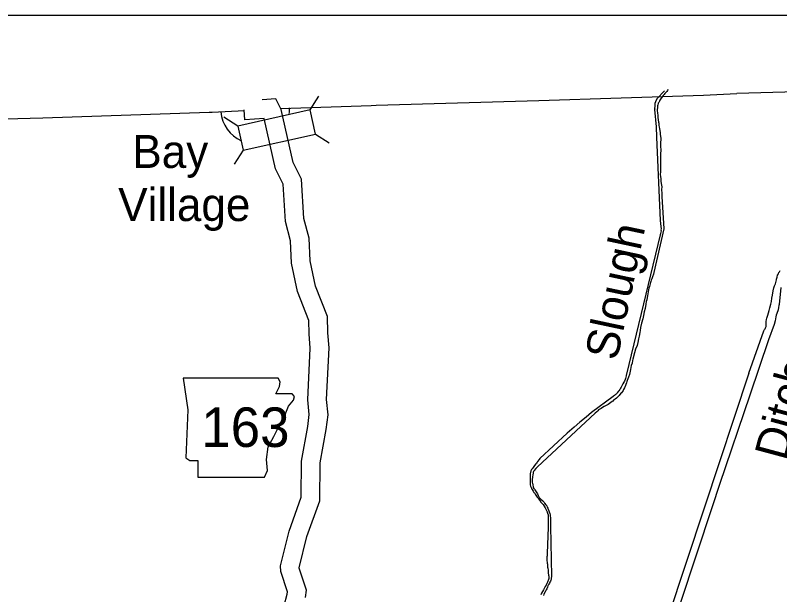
# Model space of a CAD drawing. Extents: x 1720274 to 1751788, y 372074 to 391887.
# Drawn here: x 1721650 to 1723587, y 389783 to 391250 of the extents above; entities that cross this region are included whole.
import ezdxf

# ---------------------------------------------------------------- set-up
doc = ezdxf.new("R2010")
doc.units = 0
for name, color, linetype in [('Level 10', 7, 'Continuous'), ('Level 2', 7, 'Continuous'), ('Level 20', 7, 'Continuous'), ('Level 21', 7, 'Continuous'), ('Level 24', 7, 'Continuous'), ('Level 9', 7, 'Continuous'), ('R_Draft', 7, 'Continuous')]:
    doc.layers.add(name, color=color, linetype=linetype)

msp = doc.modelspace()

# ---------------------------------------------------------------- linework, layer by layer
at = {"layer": 'Level 10'}
for points in [[(1722385.3, 389775.2), (1722387.6, 389794.5), (1722369.5, 389849.6), (1722369.5, 389850.5), (1722388.9, 389929.9), (1722421.2, 390020.6), (1722422.7, 390116.5), (1722437.8, 390201.2), (1722442.3, 390238.3), (1722438.3, 390277.1), (1722444.8, 390407.4), (1722442, 390446), (1722440.5, 390487.2), (1722410.2, 390563.9), (1722396.7, 390628.2), (1722394.2, 390685.6), (1722381.2, 390735.3), (1722375.2, 390834.5), (1722353.8, 390876.6), (1722323.9, 391011.1), (1722310.4, 391037.8), (1722275.4, 391035.3)], [(1722293, 389611.9), (1722338.6, 389784.2), (1722339.3, 389789.7), (1722322.4, 389841.3), (1722321.9, 389855.5), (1722343.5, 389943.5), (1722374, 390029.2), (1722375.3, 390121), (1722390.9, 390208.2), (1722394.6, 390238.8), (1722390.8, 390275.8), (1722397.4, 390406.8), (1722394.6, 390443.4), (1722393.4, 390477.3), (1722364.6, 390550.2), (1722349.5, 390622.2), (1722347, 390678.5), (1722334.1, 390727.8), (1722328.5, 390821.8), (1722308.8, 390860.5), (1722280.5, 390988.1), (1722231.4, 390984.6), (1722229.7, 391009.9)]]:
    msp.add_lwpolyline(points, dxfattribs=at)
at = {"layer": 'Level 2'}
for points in [[(1722322.5, 391013.9), (1722551.7, 391021.1), (1722564.3, 391022.3), (1722976.6, 391033.7), (1723393.7, 391047.3), (1723478.2, 391051.4)], [(1725918.9, 390953.1), (1725520.8, 390936.9), (1725105.9, 390920.6), (1725102.6, 390920.9), (1724681.3, 390898.6), (1724262.9, 390876.8), (1724258, 390877.1), (1723818.3, 390857.8), (1723811.7, 391060.7), (1723478.2, 391051.4)], [(1720701.8, 390842.8), (1720925, 390848.4), (1721339.8, 390867.2), (1721336.9, 390979.9), (1721719.6, 390989.9), (1722141.5, 391004.1), (1722148.7, 391004.5), (1722230.7, 391008.8)]]:
    msp.add_lwpolyline(points, dxfattribs=at)
at = {"layer": 'Level 20'}
for p, q in [((1722396.8, 391009.9), (1722419.2, 391045)), ((1722213.5, 390969.2), (1722178.3, 390991.6)), ((1722410.3, 390948.8), (1722445.5, 390926.4)), ((1722227.1, 390908.1), (1722204.7, 390872.9))]:
    msp.add_line(p, q, dxfattribs=at)
msp.add_lwpolyline([(1722227.1, 390908.1), (1722410.3, 390948.8), (1722396.8, 391009.9), (1722213.5, 390969.2)], close=True, dxfattribs=at)
at = {"layer": 'Level 21'}
msp.add_lwpolyline([(1722075.1, 390331.1), (1722087.1, 390250.9), (1722081.8, 390129.3), (1722092.5, 390122.6), (1722112.5, 390122.6), (1722112.5, 390079.9), (1722280.9, 390079.9), (1722289, 390097.2), (1722286.3, 390125.3), (1722290.3, 390157.4), (1722305, 390182.8), (1722314.3, 390201.5), (1722327.7, 390221.5), (1722335.7, 390242.9), (1722342.4, 390260.3), (1722354.4, 390275), (1722357.1, 390284.3), (1722351.8, 390291), (1722310.3, 390291), (1722319.7, 390309.7), (1722321, 390321.8), (1722315.5, 390331)], close=True, dxfattribs=at)
at = {"layer": 'Level 24'}
for start, end in [(352.9195, 2.5103), (184.1966, 246.5159)]:
    msp.add_arc((1722257.6, 391011.5), 86.9, start, end, dxfattribs=at)
at = {"layer": 'Level 9'}
for points in [[(1723294.7, 391058.5), (1723275.2, 391038.1), (1723272, 391030.5), (1723270.2, 391026), (1723270.1, 391024), (1723270, 391021.6), (1723270, 391018.9), (1723269.8, 391014.9), (1723269.9, 391011.9), (1723269.8, 391010.7), (1723273.7, 390967), (1723274.5, 390941.4), (1723283.7, 390730.4), (1723285.7, 390714.8), (1723286.2, 390709), (1723285.8, 390706.7), (1723285.9, 390703.9), (1723285.1, 390700.2), (1723284.6, 390697.5), (1723284.5, 390695.9), (1723284.1, 390693.7), (1723217.4, 390418.2), (1723197.7, 390337.5), (1723197.4, 390336.6), (1723196.9, 390333.4), (1723196.1, 390330.2), (1723194.7, 390327.4), (1723193.3, 390323.6), (1723191.6, 390320.7), (1723189.1, 390316.3), (1723187.5, 390312.8), (1723185.1, 390308.4), (1723183.5, 390305.2), (1723181.7, 390302), (1723178.8, 390298.7), (1723177.1, 390296.8), (1723175.1, 390293.7), (1723173.9, 390292.1), (1723172.2, 390290.6), (1723170.7, 390289.3), (1723168, 390286.8), (1723165.9, 390285.5), (1723164.6, 390284.6), (1723109.4, 390244.2), (1723096.5, 390232.5), (1723080.2, 390219.6), (1723065.6, 390207.1), (1723048.4, 390191.7), (1722978.9, 390127.1), (1722976.9, 390124.7), (1722973.3, 390120.3), (1722971.9, 390118.4), (1722970.4, 390115.9), (1722968.9, 390113.8), (1722965.7, 390110.1), (1722963.4, 390107.5), (1722961.9, 390105), (1722959.2, 390101.5), (1722958, 390100), (1722956.1, 390096.6), (1722954.7, 390088.8), (1722954.5, 390086.6), (1722954.4, 390083.9), (1722954.2, 390081.2), (1722954.6, 390077.7), (1722954.7, 390074.9), (1722954.7, 390072), (1722954.8, 390068.5), (1722954.4, 390065.3), (1722954.4, 390061.1), (1722955.6, 390057.3), (1722956.3, 390055.7), (1722956.8, 390054.3), (1722957.6, 390052.6), (1722958.7, 390050.1), (1722959.5, 390048.9), (1722961.7, 390045.1), (1722964, 390041.6), (1722965.1, 390040.2), (1722967.3, 390036.9), (1722969.1, 390034.3), (1722970.3, 390032.3), (1722972.1, 390029.9), (1722974.7, 390026.7), (1722977.7, 390021.7), (1722980.4, 390018.3), (1722980.7, 390017.9), (1722984.8, 390013.4), (1722986.9, 390011.1), (1722990, 390006.7), (1722992.7, 390002.4), (1722996.1, 389995.7), (1722997.3, 389992.7), (1722997.5, 389991.6), (1722997.9, 389989.4), (1722999.6, 389984.9), (1723000.1, 389981.9), (1723000.2, 389980.1), (1723000.2, 389976.6), (1723000.4, 389973), (1723000.3, 389966.7)], [(1723303.6, 391061.8), (1723302.4, 391059.3), (1723300.6, 391056.8), (1723299.3, 391054.9), (1723295.9, 391051.4), (1723294.2, 391049.5), (1723291.6, 391046.2), (1723289.8, 391044), (1723288.8, 391042.8), (1723287.4, 391041), (1723286, 391039.4), (1723284.7, 391037.3), (1723282.9, 391034.4), (1723281.7, 391032.1), (1723280.2, 391029.2), (1723278.9, 391027), (1723278.6, 391026.2), (1723277.6, 391023), (1723277, 391020.2), (1723276.8, 391017.2), (1723276.6, 391015), (1723276.4, 391011.3), (1723276.2, 391007.5), (1723276.6, 391002.3), (1723277.5, 390996.3), (1723277.5, 390990.6), (1723279.8, 390979), (1723280.2, 390976.3), (1723280.3, 390973.8), (1723280.5, 390970.9), (1723281.4, 390967.5), (1723282.1, 390961.8), (1723282.8, 390958.3), (1723283.5, 390951.8), (1723283.8, 390948.2), (1723284.2, 390943.9), (1723285.4, 390937.5), (1723284.7, 390925.2), (1723284.6, 390922.4), (1723284.7, 390918.1), (1723284.8, 390914.6), (1723285.1, 390911.2), (1723285.3, 390906.4), (1723284.8, 390900.8), (1723284.8, 390895.5), (1723285, 390889), (1723284.9, 390883.9), (1723284.9, 390878.5), (1723284.3, 390871.7), (1723284.2, 390865.3), (1723284.4, 390858.4), (1723284.2, 390852.5), (1723284, 390847.3), (1723284.7, 390840.3), (1723285.1, 390836.2), (1723285.7, 390830), (1723286.2, 390823.6), (1723287.1, 390819.3), (1723287.7, 390814.9), (1723287.5, 390808.7), (1723287.4, 390804.9), (1723287.7, 390802.2), (1723287.9, 390795.2), (1723288, 390791), (1723293.3, 390708.9), (1723268, 390598.3), (1723266.9, 390594.1), (1723264.7, 390587.8), (1723263.6, 390585), (1723262.7, 390582.6), (1723260.9, 390579.3), (1723259.9, 390576), (1723259.1, 390573.2), (1723257.2, 390566.4), (1723256.5, 390563.2), (1723255.4, 390558.7), (1723254.5, 390554.2), (1723253.4, 390549.1), (1723252.6, 390544.2), (1723251.8, 390539.7), (1723251, 390534.8), (1723249.9, 390529.4), (1723248.6, 390524.7), (1723247.1, 390517.9), (1723245.4, 390506.9), (1723243.5, 390498.6), (1723241.6, 390489.8), (1723239.8, 390481.2), (1723236.5, 390469.8), (1723234.3, 390459.5), (1723232.8, 390451.8), (1723232.1, 390446.2), (1723230.3, 390437.3), (1723228.9, 390430.6), (1723227, 390421), (1723225.2, 390413.5), (1723221.6, 390404.2), (1723218.9, 390395.2), (1723214.8, 390379.1), (1723213.8, 390375.4), (1723212.5, 390369.2)], [(1723508.8, 390343.4), (1723546, 390450.7), (1723548.3, 390454.1), (1723549.6, 390455.8), (1723551, 390458.3), (1723552, 390461.5), (1723552.3, 390463.6), (1723552.2, 390467.4), (1723552.3, 390470.1), (1723552.5, 390474.1), (1723553, 390479.8), (1723553.9, 390482.6), (1723556.4, 390490.1), (1723558.3, 390496.1), (1723560.3, 390502), (1723561.6, 390509.1), (1723563.8, 390518.1), (1723565.5, 390525.1), (1723566.8, 390533.8), (1723568.3, 390540.7), (1723570.2, 390552.3), (1723571.7, 390559.4), (1723573.5, 390564.4), (1723575.8, 390570), (1723577.7, 390576.2), (1723578.4, 390579.7), (1723578.9, 390581.7), (1723580.1, 390586.8), (1723581.4, 390591.4), (1723583.3, 390595.2), (1723584.8, 390598), (1723585.9, 390600.1), (1723588, 390603.9)], [(1723589.8, 390560.1), (1723584.9, 390517.6), (1723584.3, 390514.7), (1723583.4, 390509.9), (1723582.7, 390503.8), (1723579, 390494.2), (1723577.9, 390490.1), (1723576.8, 390485.9), (1723574.8, 390476.1), (1723572.5, 390467.1)], [(1723572.5, 390467.1), (1723558.4, 390428.3), (1723511.3, 390287.7)], [(1723212.5, 390369.2), (1723210.6, 390363), (1723209.8, 390358.3), (1723208.9, 390353.1), (1723207.6, 390348.5), (1723206.5, 390344.5), (1723205.7, 390340.3), (1723203.7, 390333.6), (1723201.9, 390329.1), (1723200.3, 390325.1), (1723199.3, 390322.4), (1723198.1, 390319.1), (1723196.9, 390315.1), (1723195.9, 390311.9), (1723193.8, 390306.6), (1723191.1, 390301.8), (1723190.1, 390300), (1723188, 390297.4), (1723185.4, 390293.9), (1723185.2, 390293.7), (1723181.9, 390289.5), (1723179.6, 390287.2), (1723178.7, 390286.2), (1723176.1, 390283.6), (1723174.9, 390282.3), (1723172.9, 390280.6), (1723169.7, 390277.8), (1723167, 390275.8), (1723165.8, 390275.2), (1723163.7, 390272.4), (1723162.3, 390271.6), (1723155.8, 390266.8), (1723152.3, 390264.1), (1723146.8, 390261.5), (1723142.2, 390259.3), (1723137.5, 390257), (1723134.1, 390254.5), (1723130.9, 390252.5), (1723127.8, 390250.3), (1723125.7, 390248), (1723122.9, 390245.9), (1723119.2, 390242.3), (1722972.6, 390106.3), (1722971, 390104.5), (1722969.1, 390101.9), (1722964.9, 390097.4), (1722963.8, 390095.3), (1722963.1, 390094.5), (1722961.9, 390092), (1722961.6, 390091.1), (1722960.8, 390085.5), (1722960.5, 390082.2), (1722960.2, 390079.9), (1722959.8, 390074.7), (1722959.8, 390073.3), (1722959.6, 390071.4), (1722959.4, 390070.6), (1722959.8, 390068.7), (1722959.8, 390067.4), (1722960.7, 390064), (1722961.1, 390062.4), (1722961.2, 390061.1), (1722961.5, 390059.7), (1722962.1, 390056.6), (1722962.3, 390053.7), (1722963.7, 390051.4), (1722965.2, 390049.7), (1722966.2, 390048), (1722967.8, 390045.5), (1722969.5, 390043), (1722971.4, 390040.2), (1722972.6, 390037.7), (1722975, 390033.5), (1722977.5, 390028.8), (1722979.6, 390026.4), (1722981.7, 390024.2), (1722986.1, 390020.4), (1722988.6, 390017.8), (1722990.9, 390014.4), (1722994, 390010.4), (1722996.3, 390007.6), (1722997.8, 390004.3), (1722998.9, 390001.6), (1723000.2, 389998.8), (1723001.6, 389995.2), (1723002.8, 389992.3), (1723004.2, 389988.2), (1723004.8, 389984.7), (1723005.2, 389983), (1723006, 389976.2), (1723006.2, 389973.7), (1723005.9, 389956.1), (1723008.5, 389829.8), (1723008.1, 389827), (1723008, 389825.5), (1723007.8, 389822.8), (1723007.2, 389820.9), (1723006.6, 389819.2), (1723005.8, 389816.9), (1723004.4, 389814), (1723003.1, 389811.9)], [(1723508.8, 390343.4), (1723395.8, 390004.3), (1723255.8, 389581.2), (1723120.8, 389164.5), (1723064.2, 388990), (1723038.2, 388901.8)], [(1723511.3, 390287.7), (1723434.4, 390061.8), (1723415.7, 390004.8), (1723049.4, 388901.4)], [(1723000.3, 389966.7), (1723000.4, 389964), (1723000.2, 389961.9), (1722999.8, 389958.2), (1722999.8, 389954), (1722997.8, 389886.7), (1722997.6, 389885), (1722997.1, 389880.8), (1722997, 389878.4), (1722996.8, 389875.7), (1722996.7, 389874.5), (1722996.8, 389870.5), (1722997, 389868.6), (1722997.4, 389865), (1722997.8, 389862.6), (1722998.1, 389860.3), (1722998.6, 389857.3), (1722998.6, 389852.7), (1722998.9, 389849.5), (1722999.8, 389844.9), (1723000.2, 389841.3), (1723000.3, 389839.1), (1723000.4, 389837.7), (1723001, 389832.1), (1723001.3, 389829.6), (1723001.5, 389828), (1723001.5, 389825.7), (1723001.5, 389823.6), (1723001.1, 389821.2), (1723000, 389818.3), (1722999.3, 389816.9), (1722998.4, 389814.5), (1722996.5, 389810.9), (1722994.6, 389807.2), (1722992.5, 389803.8), (1722990.9, 389799.8), (1722988.5, 389795.3), (1722983.4, 389786.9), (1722981.6, 389782.4)], [(1723003.1, 389811.9), (1723001.6, 389809), (1723000.1, 389806.3), (1722999.5, 389804.7), (1722998.5, 389801.5), (1722996.6, 389797.4), (1722995.1, 389795), (1722992.4, 389789.7), (1722989.3, 389783.9), (1722987.8, 389780.8)]]:
    msp.add_lwpolyline(points, dxfattribs=at)
at = {"layer": 'R_Draft'}
msp.add_lwpolyline([(1720610.3, 391249.6), (1726741.8, 391249.6), (1726741.8, 384893.1), (1720610.3, 384893.1)], close=True, dxfattribs=at)

# ---------------------------------------------------------------- texts
at = {"layer": 'Level 21'}
msp.add_text('163', height=100.11, dxfattribs=at).set_placement((1722121.3, 390156.7))
at = {"layer": 'Level 24'}
for s, p in [('Bay', (1721946.5, 390863.1)), ('Village', (1721910.7, 390728.7))]:
    msp.add_text(s, height=83.42, dxfattribs=at).set_placement(p)
at = {"layer": 'Level 9'}
for s, rotation, p in [('Slough', 78, (1723174.2, 390372.9)), ('Ditch', 75, (1723602.5, 390119.3))]:
    msp.add_text(s, height=83.42, rotation=rotation, dxfattribs=at).set_placement(p)

doc.saveas('drawing.dxf')
